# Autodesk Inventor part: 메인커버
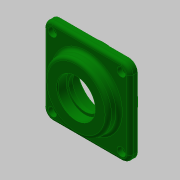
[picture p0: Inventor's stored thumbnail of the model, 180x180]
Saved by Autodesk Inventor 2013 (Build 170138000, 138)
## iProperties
Created: 2018-09
Part Number: 메인커버
Material: 알루미늄 6061
Document SubType Name: Modeling
Designer: mduedu
Density: 2.71 g/cm^3
Mass: 178.463 g
Surface Area: 197.883 cm^2
Volume: 65.8536 cm^3
Author: mduedu
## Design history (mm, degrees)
sketch "스케치1"
  geometry: L1 (-40, -40)-(40, -40); L2 (40, -40)-(40, 40); L3 (40, 40)-(-40, 40); L4 (-40, 40)-(-40, -40); L5 (-40, -40)-(40, 40); L6 (40, -40)-(-40, 40); 1 further point
  constraints: 12 end point, 2 midpoint, 2 parallel, 1 horizontal, 1 perpendicular
  dimensions: "d0" = 80 distance of L3.end L2.end; "d1" = 80 distance of L2.end L1.end
extrude "돌출1" new body sketch "스케치1" distance "d2" = 7; taper "d3" = 0 deg
sketch "스케치2"
  geometry: C1 r 30 at (0, 0); 1 further point
  constraints: 1 centre point, 1 coincident
  dimensions: "d4" = 60 diameter of C1
extrude "돌출2" join sketch "스케치2" distance "d5" = 10; taper "d6" = 0 deg
sketch "스케치3"
  geometry: C1 r 32.5 at (0, 0); 1 further point
  constraints: 1 centre point, 1 coincident
  dimensions: "d7" = 65 diameter of C1
extrude "돌출3" join sketch "스케치3" distance "d8" = 9; taper "d9" = 0 deg
sketch "스케치4"
  geometry: L1 (-32.5, -9)-(32.5, -9) reference; L2 (30, 17)-(-30, 17) reference; L3 (0, 17)-(0, -9); L4 (0, -9)-(23.5, -9); L5 (23.5, -9)-(23.5, 5); L6 (23.5, 5)-(0, 5); L7 (0, 5)-(0, -9); L8 (0, 5)-(15, 5); L9 (15, 5)-(15, 8.7); L10 (15, 8.7)-(0, 8.7); L11 (0, 8.7)-(0, 5); L12 (0, 8.7)-(17.5, 8.7); L13 (17.5, 8.7)-(17.5, 17); L14 (17.5, 17)-(0, 17); L15 (0, 17)-(0, 8.7); 1 further point
  constraints: 26 end point, 6 parallel, 3 horizontal, 3 perpendicular, 2 midpoint, 1 point on line
  dimensions: "d10" = 14 distance of L4.end L5.end; "d12" = 8.3 distance of L12.end L13.end; "d13" = 35 diameter of L13 L3; "d14" = 30 diameter of L9 L3; "d15" = 47 diameter of L5 L3
revolve "회전1" sketch "스케치4" stored, may be unused: angle "d16" = 90 deg
fillet "모깎기1" dims "d17" = 8
fillet "모깎기2" dims "d18" = 3
fillet "모깎기3" dims "d19" = 3
chamfer "모따기1" distance "d20" = 0.8; stored, may be unused: second distance "d21" = 2, angle "d22" = 30 deg
chamfer "모따기2" distance "d23" = 1; stored, may be unused: second distance "d24" = 2, angle "d25" = 30 deg
fillet "모깎기4" dims "d26" = 0.3
sketch "스케치5"
  geometry: A1 r 8 centre (-32, 32) between (-32, 40) and (-40, 32) reference; A2 r 8 centre (-32, -32) between (-40, -32) and (-32, -40) reference; A3 r 8 centre (32, -32) between (32, -40) and (40, -32) reference; A4 r 8 centre (32, 32) between (40, 32) and (32, 40) reference; 5 further points
  constraints: 4 coincident
hole "구멍1" sketch "스케치5" at (-32, 32), (32, 32), (32, -32), (-32, -32) diameter "d27" = 4.5; stored, may be unused: countersink angle "d31" = 90 deg, drill point angle "d33" = 118 deg; dims "d28" = 6, "d29" = 8, "d30" = 4.4, "d32" = 8
node "솔리드1"
